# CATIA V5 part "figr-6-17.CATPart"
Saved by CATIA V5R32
Part number: Part1
Bounding box of the stored display mesh (mm): x 0 to 150, y -70 to 70, z -150 to 69.804
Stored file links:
  D:\PROJECTS\Project 2022\CATIA V5 6R 2022\Resources\Part Files\c06_catia_v5_6r2022_prt\figr-6-17.CATPart
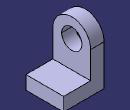
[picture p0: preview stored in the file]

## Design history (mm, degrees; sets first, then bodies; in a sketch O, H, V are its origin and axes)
Body1 (main body)
  Sketch1 on yz-plane, origin (0, 0, 0), H (0, 1, 0), V (0, 0, 1)
    arc A1 centre (0, 0) radius 70 from (70, 0) to (-70, 0) ccw
    point P1 (70, 0)
    point P2 (-70, 0)
    line L1 (-70, 0) -> (-70, -150)
    line L2 (-70, -150) -> (70, -150)
    line L3 (70, -150) -> (70, 0)
    circle A2 centre (0, 0) radius 37.5
    radius A1 = 70
    radius A2 = 37.5
    distance O L2 = 150
    coincidence: P1 H, P2 H
    tangency: L1 A1, L3 A1
    horizontal: L2 H
  Pad1: profile Sketch1, direction (1, 0, 0), length 50
  Sketch2 on face of Pad1, origin (50, 0, 0), H (0, 1, 0), V (0, 0, 1)
    line L1 (-70, -150) -> (70, -150)
    line L2 (70, -150) -> (70, -100)
    line L3 (70, -100) -> (-70, -100)
    line L4 (-70, -100) -> (-70, -150)
    reference projected line E1 (-70, -150) -> (70, -150) from edge [face of Pad1 | face of Pad1]
    reference projected line E2 (-70, 0) -> (-70, -150) from edge [face of Pad1 | face of Pad1]
    reference projected line E3 (70, -150) -> (70, 0) from edge [face of Pad1 | face of Pad1]
    length L2 = 50
    horizontal: L1 H, L3 H
    vertical: L2 V, L4 V
    coincidence: L1 E1, E2 L4, L2 E3
  Pad2: profile Sketch2, direction (1, 0, 0), length 100
  Sketch3 on face of Pad1, origin (50, 0, 0), H (0, 1, 0), V (0, 0, 1)
    point P1 (45.5554, 53.148)
    reference projected arc E1 centre (0, 0) radius 70 from (70, 0) to (-70, 0) ccw from edge [face of Pad1 | face of Pad1]
    coincidence: P1 E1
  Sketch4 on face of Pad2, origin (0, 0, -100), H (1, 0, 0), V (0, 1, 0)
    point P1 (110, 20)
